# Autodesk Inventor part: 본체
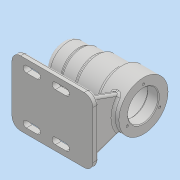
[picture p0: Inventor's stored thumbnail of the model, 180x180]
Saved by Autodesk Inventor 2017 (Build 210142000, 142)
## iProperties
Part Number: 본체
Material: 일반
Document SubType Name: Modeling
Designer: MRC
Density: 1 g/cm^3
Appearance: 기본값
Author: MRC
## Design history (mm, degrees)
sketch "스케치1"
  geometry: L1 (0, 0)-(0, 25); L2 (0, 25)-(24, 25); L3 (24, 25)-(24, 27); L4 (24, 27)-(46, 27); L5 (46, 27)-(46, 30); L6 (46, 30)-(80, 30); L7 (80, 30)-(80, 34); L8 (80, 34)-(112, 34); L9 (112, 34)-(112, 21); L10 (112, 21)-(97, 21); L11 (97, 21)-(97, 24); L12 (97, 24)-(43, 24); L13 (43, 24)-(43, 21); L14 (43, 21)-(31, 21); L15 (31, 21)-(31, 17.5); L16 (31, 17.5)-(13, 17.5); L17 (13, 17.5)-(13, 16); L18 (13, 16)-(9, 16); L19 (9, 16)-(9, 10.5); L20 (9, 10.5)-(6, 10.5); L21 (6, 10.5)-(6, 0); L22 (6, 0)-(0, 0)
  constraints: 44 end point, 18 perpendicular, 2 horizontal, 2 vertical, 1 collinear
  dimensions: "d0" = 25 distance between parallel lines of L22 L2; "d1" = 27 distance between parallel lines of L22 L4; "d2" = 30 distance between parallel lines of L22 L6; "d3" = 34 distance between parallel lines of L22 L8; "d4" = 24 distance of L1.end L2.end; "d5" = 46 distance between parallel lines of L1 L5; "d6" = 80 distance between parallel lines of L1 L7; "d7" = 112 distance between parallel lines of L9 L1; "d8" = 15 distance of L9.end L10.end; "d9" = 54 distance of L11.end L12.end; "d10" = 12 distance of L13.end L14.end; "d11" = 18 distance of L15.end L16.end; "d12" = 4 distance of L17.end L18.end; "d13" = 3 distance of L19.end L20.end; "d14" = 24 distance between parallel lines of L22 L12; "d15" = 21 distance between parallel lines of L22 L10; "d16" = 17.5 distance between parallel lines of L22 L16; "d17" = 16 distance between parallel lines of L22 L18; "d18" = 10.5 distance between parallel lines of L22 L20
revolve "회전1" sketch "스케치1" stored, may be unused: angle "d19" = 90 deg
fillet "모깎기1" dims "d20" = 8
node "작업 평면1"
sketch "스케치2"
  geometry: L1 (0, 45)-(-112, 45); L2 (-112, 45)-(-112, -45); L3 (-112, -45)-(0, -45); L4 (0, -45)-(0, 45); L5 (0, 45)-(-112, -45); L6 (-112, 45)-(0, -45); 3 further points
  constraints: 12 end point, 4 midpoint, 2 parallel, 1 horizontal, 1 horizontal alignment, 1 perpendicular
  dimensions: "d22" = 112 distance of L2.end L3.end; "d23" = 90 distance of L3.end L1.start
extrude "돌출1" join sketch "스케치2" distance "d24" = 8; taper "d25" = 0 deg
sketch "스케치3"
  geometry: L1 (112, -45)-(112, 45) reference; L2 (0, 45)-(0, -45) reference; L3 (27, -4)-(104, -4); L4 (104, -4)-(104, 4); L5 (104, 4)-(27, 4); L6 (27, 4)-(27, -4); L7 (27, -4)-(104, 4); L8 (104, -4)-(27, 4); 4 further points
  constraints: 12 end point, 4 midpoint, 2 parallel, 1 horizontal, 1 horizontal alignment, 1 perpendicular
  dimensions: "d26" = 8 distance between parallel lines of L1 L4; "d27" = 77 distance of L4.end L5.end; "d28" = 8 distance of L5.end L3.start
extrude "돌출2" join sketch "스케치3" stored distance "d29" = 8; taper "d30" = 0 deg
sketch "스케치4"
  geometry: L1 (-41, -8)-(-41, 0) reference; L2 (-41, 0)-(0, 0) reference; L3 (0, 0)-(0, 28.236) reference; L4 (8, 28.236)-(8, 0) reference; L5 (8, 0)-(49, 0) reference; L6 (49, 0)-(49, -8) reference; L7 (49, -8)-(-41, -8) reference; L8 (0, 0)-(8, 0) reference; L9 (-19.409, 37.342)-(-33, 0); C1 r 21 at (4, 62) reference; A1 r 34 centre (4, 62) between (8, 28.236) and (0, 28.236) reference; A2 r 34 centre (4, 62) between (0, 28.236) and (8, 28.236) reference
  constraints: 2 end point, 1 point on circle, 1 point on line
  dimensions: "d31" = 8 distance from line of L1 L9.end; "d32" = 110 deg angle of L2 L9
extrude "돌출3" join sketch "스케치4" distance "d33" = 8; taper "d34" = 0 deg
sketch "스케치5"
  geometry: C1 r 21 at (0, 0) reference; 1 further point
  constraints: 1 horizontal alignment
  dimensions: "d35" = 26 distance of C1.centre point (-26, 0)
hole "구멍1" sketch "스케치5" at (-26, 0) diameter "d36" = 3.242; stored, may be unused: countersink angle "d40" = 90 deg, drill point angle "d42" = 118 deg; dims "d37" = 8, "d38" = 4, "d39" = 2, "d41" = 11
sketch "스케치6"
  geometry: L1 (0, 45)-(0, -45) reference; L2 (20, -33)-(35, -33); L3 (24, -25)-(24, 25) reference; L4 (20, -28.5)-(35, -28.5); L5 (35, -37.5)-(20, -37.5); L6 (60, -33)-(75, -33); L7 (60, -28.5)-(75, -28.5); L8 (75, -37.5)-(60, -37.5); A1 r 4.5 centre (20, -33) between (20, -28.5) and (20, -37.5); A2 r 4.5 centre (35, -33) between (35, -37.5) and (35, -28.5); A3 r 4.5 centre (60, -33) between (60, -28.5) and (60, -37.5); A4 r 4.5 centre (75, -33) between (75, -37.5) and (75, -28.5); 3 further points
  constraints: 16 end point, 8 point on circle, 8 tangent, 4 centre point, 2 midpoint, 2 parallel, 1 horizontal, 1 horizontal alignment, 1 perpendicular
  dimensions: "d46" = 20 distance from line of L1 L2.start; "d47" = 15 distance of L2.start L2.end; "d48" = 33 distance from line of point (0, 0) L2; "d49" = 4.5 radius of A1; "d50" = 25 distance of L2.end L6.start; "d51" = 15 distance of L6.start L6.end; "d52" = 4.5 radius of A3
extrude "돌출4" cut sketch "스케치6" distance "d53" = 8; taper "d54" = 0 deg
feature "면 기울기1" dims angle "d55" = 15 deg
fillet "모깎기2" dims "d56" = 12
fillet "모깎기3" dims "d57" = 3
fillet "모깎기4" dims "d58" = 3
fillet "모깎기5" dims "d59" = 3
fillet "모깎기6" dims "d60" = 3
fillet "모깎기7" dims "d61" = 3
fillet "모깎기8" dims "d62" = 0.3
sketch "스케치7"
  geometry: L1 (0, 33)-(0, -33) reference; 3 further points
  constraints: 1 horizontal alignment, 1 midpoint, 1 other
  dimensions: "d63" = 12 distance from line of L1 point (12, 0)
feature "엠보싱1" sketch "스케치7" dims "d0" = 25, "d1" = 27, "d2" = 30, "d3" = 34, "d4" = 24, "d5" = 46, "d6" = 80, "d7" = 112, "d8" = 15, "d9" = 54, "d10" = 12, "d11" = 18, "d12" = 4, "d13" = 3, "d14" = 24, "d15" = 21, "d16" = 17.5, "d17" = 16, "d18" = 10.5, "d64" = 0.5, "d65" = 0
chamfer "모따기1" distance "d66" = 1; stored, may be unused: second distance "d67" = 2, angle "d68" = 45 deg
node "솔리드1"
mirror "미러1"
pattern_circular "원형 패턴1" dims angle "d44" = 360 deg
mirror "미러2"
node "절단 모서리 투영1"
